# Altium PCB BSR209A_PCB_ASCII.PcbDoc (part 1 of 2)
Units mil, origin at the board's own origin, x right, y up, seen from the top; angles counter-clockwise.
Board outline 3820.03 x 2030.03 mil, 4 copper layers (Top Layer, MidLayer1, MidLayer2, Bottom Layer), stack 59.4 mil thick; 68 components, 18 nets, 122 pads, 73 vias.
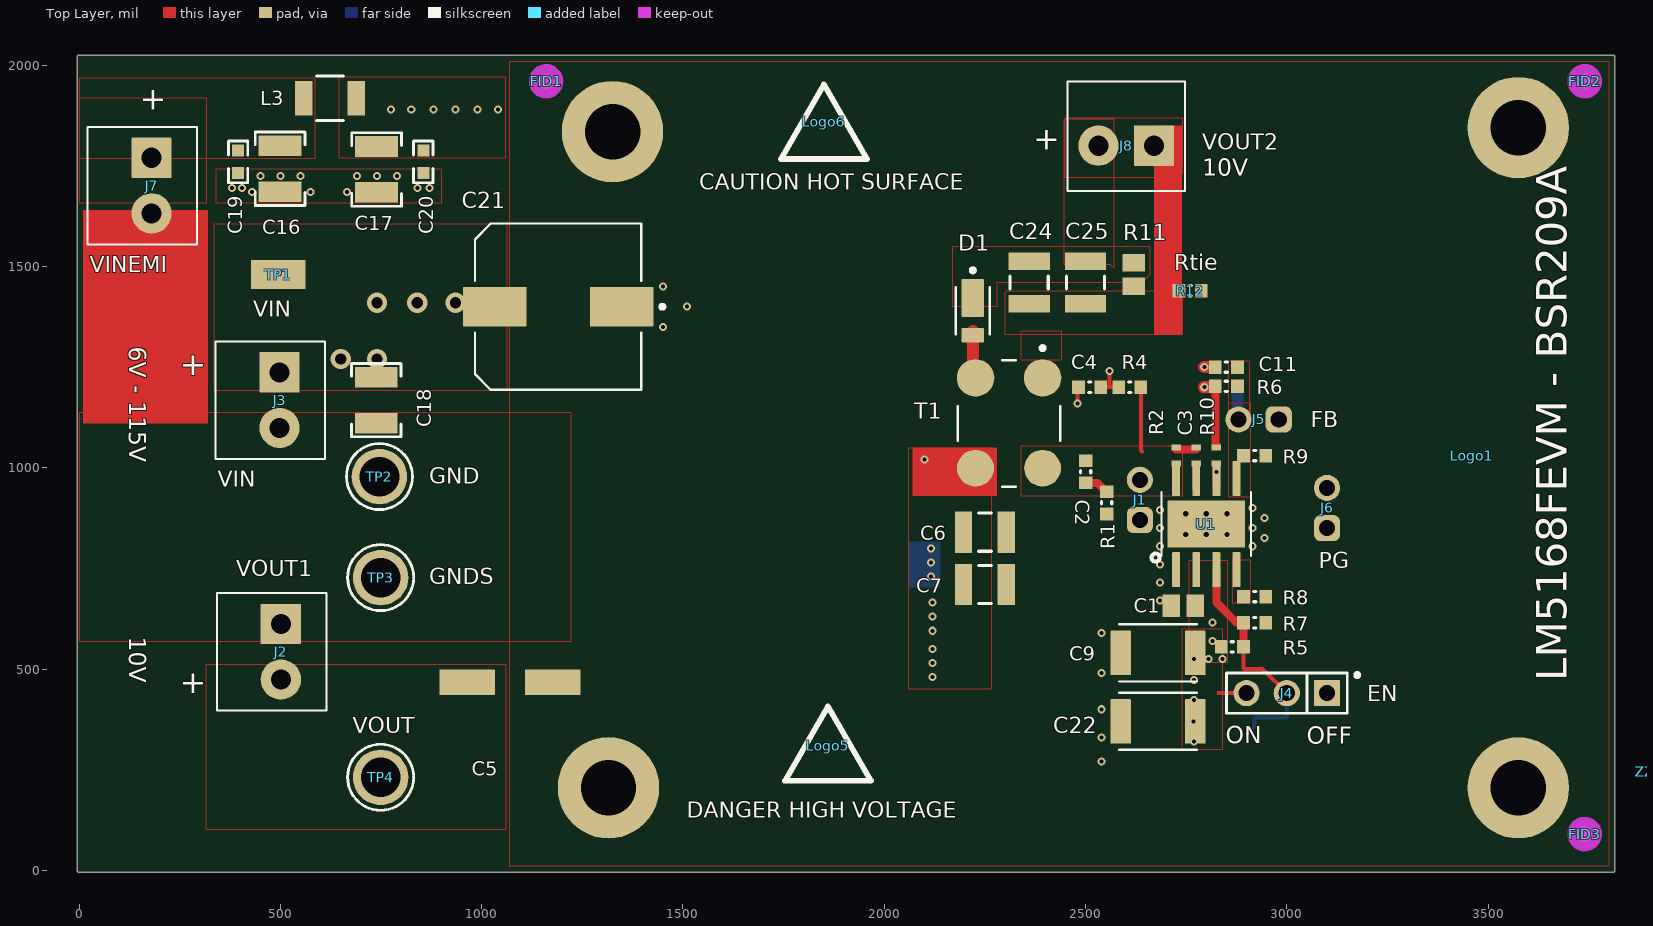
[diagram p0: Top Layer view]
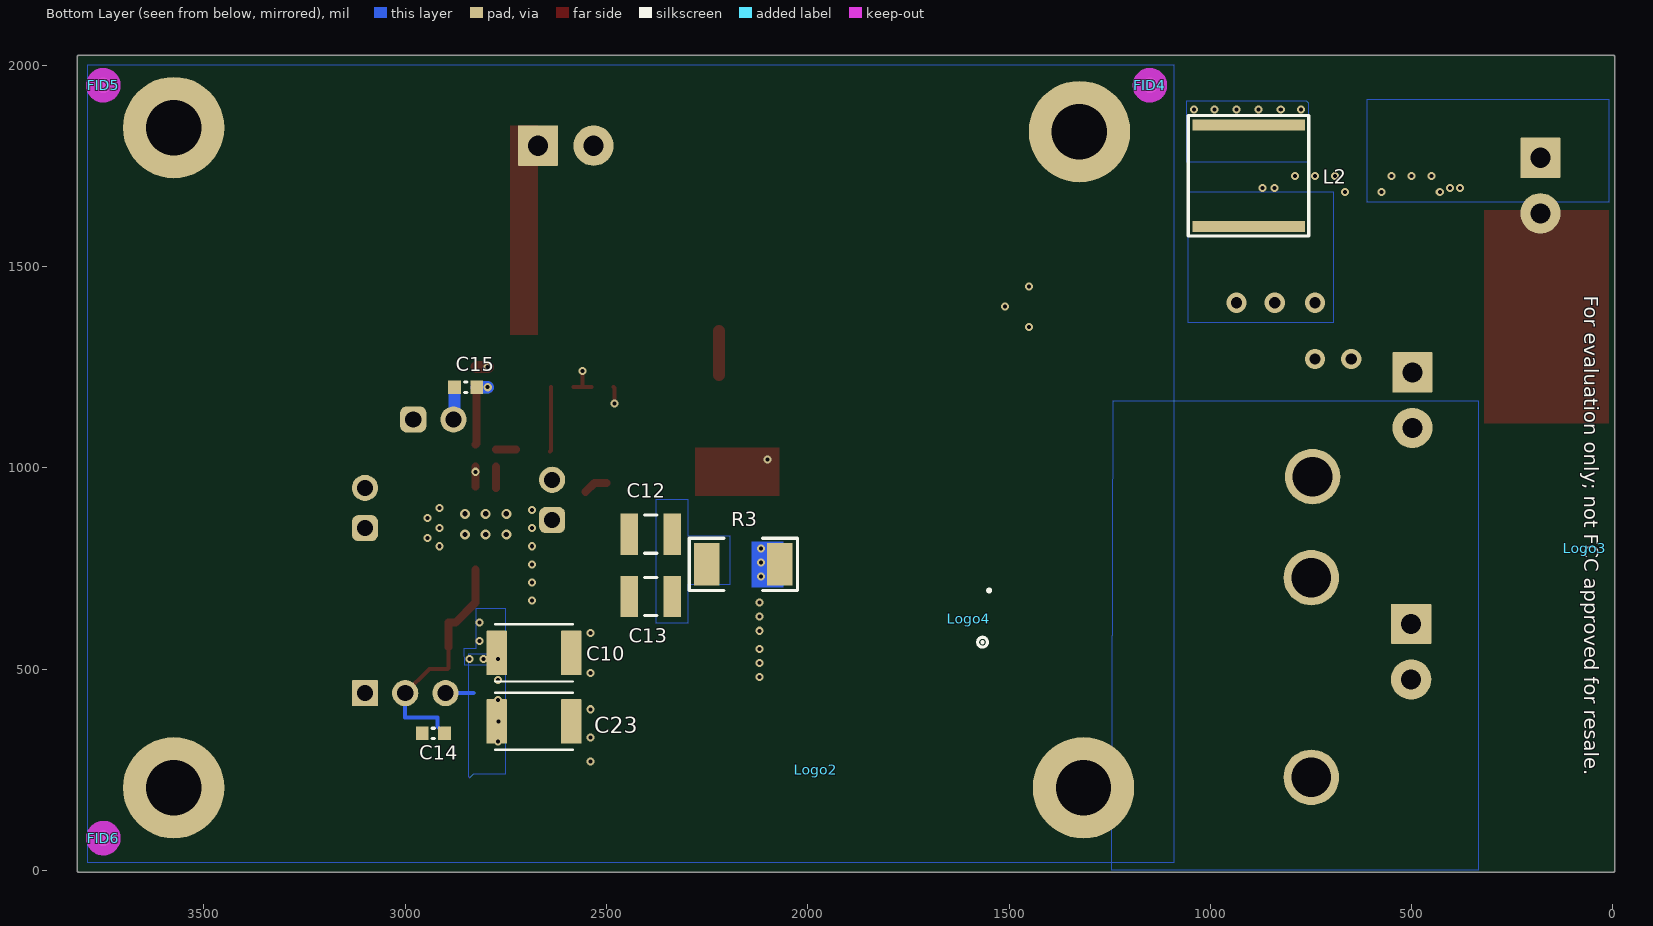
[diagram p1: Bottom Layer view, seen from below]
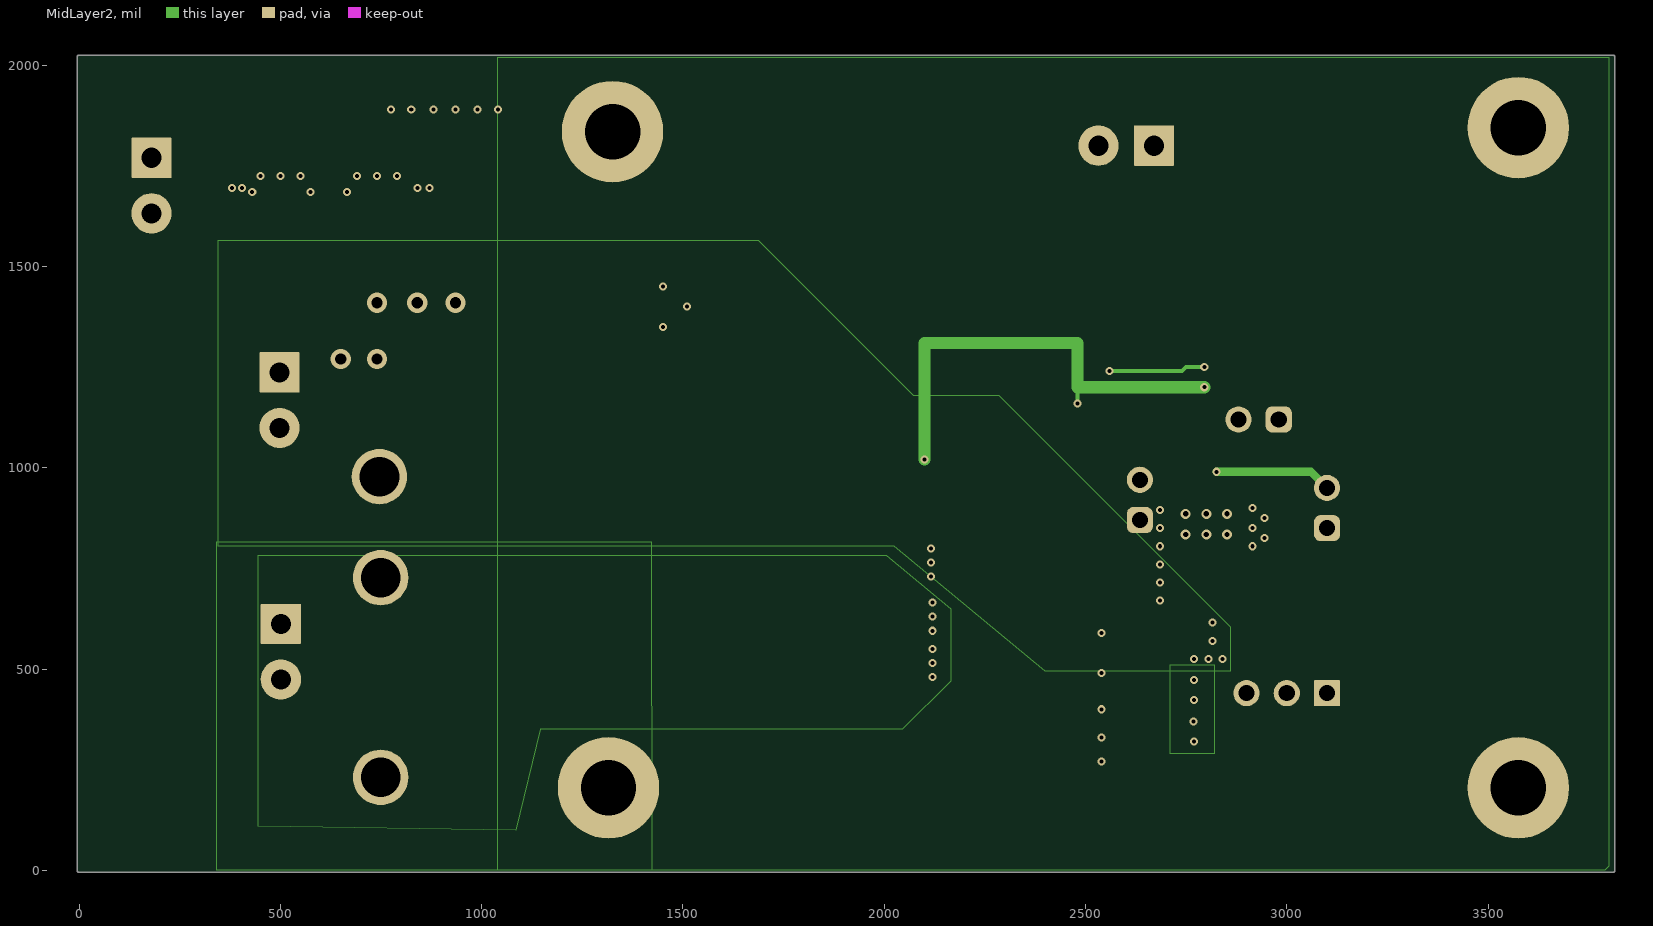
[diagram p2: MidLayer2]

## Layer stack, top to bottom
Top Solder: solder mask 0.4, Solder Resist, Dk 3.5
Top Layer: signal copper 2.8
Dielectric1: core 10, FR-4, Dk 4.8
MidLayer1: signal copper 1.4
Dielectric2: prepreg 31, FR-4, Dk 4.8
MidLayer2: signal copper 1.4
Dielectric3: core 10, FR-4, Dk 4.8
Bottom Layer: signal copper 2.8
Bottom Solder: solder mask 0.4, Solder Resist, Dk 3.5

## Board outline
0,-5.01 cw(c0,0) -5.02,0 -5.02,2020 cw(c0,2020) 0,2025.02 3810,2025.02 cw(c3810,2020) 3815.02,2020 3815.02,0 cw(c3810,0) 3810,-5.01 318,-5.01 cw(c318,0) 316.5,-4.79 cw(c315,0) 315,-5.01

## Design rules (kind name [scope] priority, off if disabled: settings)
AcuteAngle [All] p0: scope1count=1 scope1_0_kind=Board scope1_0_value=Board scope2count=1 scope2_0_kind=Board scope2_0_value=Board commentlength=0 minimum=4.50000000000000E+0001
AcuteAngle [All] p1: minimum=4.50000000000000E+0001 checktracksonly=TRUE
AssemblyTestPointUsage [All] p0: scope1count=1 scope1_0_kind=Board scope1_0_value=Board scope2count=1 scope2_0_kind=Board scope2_0_value=Board commentlength=0
AssemblyTestPointUsage [All] p1: valid=2
AssemblyTestpoint [All] p0: scope1count=1 scope1_0_kind=Board scope1_0_value=Board scope2count=1 scope2_0_kind=Board scope2_0_value=Board commentlength=0
BoardOutlineClearance [All] p0 off: scope1count=1 scope1_0_kind=Board scope1_0_value=Board scope2count=1 scope2_0_kind=Board scope2_0_value=Board commentlength=172 gap=20 // Protel DXP Scope 1 Expression Was: OnCopper and Not InComponentClass('Logo') and not InComponentClass('FiducialMark') and not InRegion(1000,500,4000,800) and not InPoly
BoardOutlineClearance BoardOutlineClearance_Poly [All] p0 off: scope1count=1 scope1_0_kind=Board scope1_0_value=Board scope2count=1 scope2_0_kind=Board scope2_0_value=Board commentlength=58 gap=15 // Protel DXP Scope 1 Expression Was: OnCopper and IsPoly
BoardOutlineClearance BoardOutlineClearance_MountingHoles [All] p0 off: scope1count=1 scope1_0_kind=Board scope1_0_value=Board scope2count=1 scope2_0_kind=Board scope2_0_value=Board commentlength=86 gap=40 // Protel DXP Scope 1 Expression Was: OnCopper and InComponentClass('Mounting Holes')
BoardOutlineClearance BoardOutlineClearance_MountingHoles [OnCopper and InComponentClass('Mounting Holes')] p1: gap=40 ignorepadtopadclearanceinfootprint=FALSE
BoardOutlineClearance BoardOutlineClearance_Poly [OnCopper and IsPoly] p2: gap=15 ignorepadtopadclearanceinfootprint=FALSE
BoardOutlineClearance [OnCopper and Not InComponentClass('Logo') and not InComponentClass('FiducialMark') and not InRegion(1000,500,4000,800) and not InPoly] p3: gap=20 ignorepadtopadclearanceinfootprint=FALSE
Clearance [All] p0: scope1count=1 scope1_0_kind=Board scope1_0_value=Board scope2count=1 scope2_0_kind=Board scope2_0_value=Board commentlength=0 gap=5
Clearance Clearance_FiducialMark [All] p0 off: scope1count=1 scope1_0_kind=Board scope1_0_value=Board scope2count=1 scope2_0_kind=Board scope2_0_value=Board commentlength=81 gap=0 // Protel DXP Scope 2 Expression Was: IsPad and InComponentClass('FiducialMark')
Clearance Clearance_Poly [All] p0 off: scope1count=1 scope1_0_kind=Board scope1_0_value=Board scope2count=1 scope2_0_kind=Board scope2_0_value=Board commentlength=48 gap=10 // Protel DXP Scope 1 Expression Was: InPolygon
Clearance Clearance_Keepouts [All] p0 off: scope1count=1 scope1_0_kind=Board scope1_0_value=Board scope2count=1 scope2_0_kind=Board scope2_0_value=Board commentlength=99 gap=0 // Protel DXP Scope 2 Expression Was: ((IsTrack Or IsArc) And Not InPoly) And IsFree and IsKeepOut
Clearance Clearance_Keepouts [((IsTrack Or IsArc) And Not InPoly) And IsFree and IsKeepOut vs ((IsTrack Or IsArc) And Not InPoly) And IsFree and IsKeepOut] p1: gap=0 ignorepadtopadclearanceinfootprint=TRUE
Clearance Clearance_Poly [InPolygon] p2: gap=10 ignorepadtopadclearanceinfootprint=TRUE except(0: Arc-Hole Track-Hole SMDPad-Hole THPad-Hole Via-Hole Fill-Hole Poly-Hole Region-Hole Text-Hole)
Clearance Clearance_FiducialMark [IsKeepOut and InComponentClass('FiducialMark') vs IsPad and InComponentClass('FiducialMark')] p3: gap=0 ignorepadtopadclearanceinfootprint=TRUE
Clearance [All] p4: gap=5 ignorepadtopadclearanceinfootprint=TRUE except(0: Arc-Hole Track-Hole SMDPad-Hole THPad-Hole Via-Hole Fill-Hole Poly-Hole Region-Hole Text-Hole)
ComponentClearance [All] p0: scope1count=1 scope1_0_kind=Board scope1_0_value=Board scope2count=1 scope2_0_kind=Board scope2_0_value=Board commentlength=0 gap=10 collisioncheckmode=3
ComponentClearance ComponentClearance_THtoTH [All] p0 off: scope1count=1 scope1_0_kind=Board scope1_0_value=Board scope2count=1 scope2_0_kind=Board scope2_0_value=Board commentlength=54 gap=10 collisioncheckmode=3 // Protel DXP Scope 2 Expression Was: IsThruComponent
ComponentClearance ComponentClearance_THtoSMT [All] p0 off: scope1count=1 scope1_0_kind=Board scope1_0_value=Board scope2count=1 scope2_0_kind=Board scope2_0_value=Board commentlength=53 gap=10 collisioncheckmode=3 // Protel DXP Scope 2 Expression Was: IsSMTComponent
ComponentClearance ComponentClearance_SmallPassives [All] p0 off: scope1count=1 scope1_0_kind=Board scope1_0_value=Board scope2count=1 scope2_0_kind=Board scope2_0_value=Board commentlength=508 gap=10 collisioncheckmode=3 // Protel DXP Scope 2 Expression Was: HasFootprint('0201*') or HasFootprint('0402*') or HasFootprint('0508') or HasFootprint('0603*') or HasFootprint('0612') or HasFootprint('0805*') or HasFootprint('0815*') or HasFootprint('0830*') or HasFootprint('1206*') or HasFootprint('1210*') or HasFootprint('1808*') or HasFootprint('1812*') or HasFootprint('1825*') or HasFootprint('2010*') or HasFootprint('2220*') or HasFootprint('2225*') or HasFootprint('2512*') or HasFootprint('2728*') or HasFootprint('3518*')
ComponentClearance ComponentClearance_MountingHoles [All] p0: scope1count=1 scope1_0_kind=ComponentClass scope1_0_value="Mounting Holes" scope2count=1 scope2_0_kind=Board scope2_0_value=Board commentlength=0 gap=10 collisioncheckmode=3
ComponentClearance ComponentClearance_ScrewToNut [All] p0 off: scope1count=1 scope1_0_kind=Board scope1_0_value=Board scope2count=1 scope2_0_kind=Board scope2_0_value=Board commentlength=71 gap=5 collisioncheckmode=3 // Protel DXP Scope 2 Expression Was: (HasFootprint('Keystone_1902C'))
ComponentClearance ComponentClearance_Logo [All] p0: scope1count=1 scope1_0_kind=ComponentClass scope1_0_value=Logo scope2count=1 scope2_0_kind=Board scope2_0_value=Board commentlength=0 gap=10 collisioncheckmode=3
ComponentClearance ComponentClearance_Shunt [All] p0: scope1count=1 scope1_0_kind=ComponentClass scope1_0_value=Header scope2count=1 scope2_0_kind=ComponentClass scope2_0_value=Shunt commentlength=0 gap=0 collisioncheckmode=3
ComponentClearance ComponentClearance_MountingHoles_FiducialMarks [All] p0: scope1count=1 scope1_0_kind=ComponentClass scope1_0_value="Mounting Holes" scope2count=1 scope2_0_kind=ComponentClass scope2_0_value=FiducialMark commentlength=0 gap=10 collisioncheckmode=3
ComponentClearance ComponentClearance_MountingHoles_FiducialMarks [InComponentClass('Mounting Holes') vs InComponentClass('FiducialMark')] p1: gap=10 collisioncheckmode=3 verticalgap=10 showdistances=FALSE
ComponentClearance ComponentClearance_Shunt [InComponentClass('Header') vs InComponentClass('Shunt')] p2: gap=0 collisioncheckmode=3 verticalgap=0 showdistances=FALSE
ComponentClearance ComponentClearance_Logo [InComponentClass('Logo')] p3: gap=10 collisioncheckmode=3 verticalgap=10 showdistances=FALSE
ComponentClearance ComponentClearance_ScrewToNut [(HasFootprint('NY PMS 440 0025 PH')) vs (HasFootprint('Keystone_1902C'))] p4: gap=5 collisioncheckmode=3 verticalgap=10 showdistances=FALSE
ComponentClearance ComponentClearance_MountingHoles [InComponentClass('Mounting Holes')] p5: gap=10 collisioncheckmode=3 verticalgap=100000 showdistances=FALSE
ComponentClearance ComponentClearance_SmallPassives [HasFootprint('0201*') or HasFootprint('0402*') or HasFootprint('0508') or HasFootprint('0603*') or HasFootprint('0612') or HasFootprint('0805*') or HasFootprint('0815*') or HasFootprint('0830*') or HasFootprint('1206*') or HasFootprint('1210*') or HasFootprint('1808*') or HasFootprint('1812*') or HasFootprint('1825*') or HasFootprint('2010*') or HasFootprint('2220*') or HasFootprint('2225*') or HasFootprint('2512*') or HasFootprint('2728*') or HasFootprint('3518*') vs HasFootprint('0201*') or HasFootprint('0402*') or HasFootprint('0508') or HasFootprint('0603*') or HasFootprint('0612') or HasFootprint('0805*') or HasFootprint('0815*') or HasFootprint('0830*') or HasFootprint('1206*') or HasFootprint('1210*') or HasFootprint('1808*') or HasFootprint('1812*') or HasFootprint('1825*') or HasFootprint('2010*') or HasFootprint('2220*') or HasFootprint('2225*') or HasFootprint('2512*') or HasFootprint('2728*') or HasFootprint('3518*')] p6: gap=10 collisioncheckmode=3 verticalgap=10 showdistances=FALSE
ComponentClearance ComponentClearance_THtoSMT [IsThruComponent vs IsSMTComponent] p7: gap=10 collisioncheckmode=3 verticalgap=30 showdistances=FALSE
ComponentClearance ComponentClearance_THtoTH [IsThruComponent vs IsThruComponent] p8: gap=10 collisioncheckmode=3 verticalgap=30 showdistances=FALSE
ComponentClearance [All] p9: gap=10 collisioncheckmode=3 verticalgap=30 showdistances=FALSE
DiffPairsRouting [All] p0: scope1count=1 scope1_0_kind=Board scope1_0_value=Board scope2count=1 scope2_0_kind=Board scope2_0_value=Board commentlength=0
DiffPairsRouting [All] p1: maxlimit=100 minlimit=10 mostfreqgap=10 toplayer_minwidth=15 toplayer_maxwidth=15 toplayer_prefwidth=15 midlayer1_minwidth=15 midlayer1_maxwidth=15 midlayer1_prefwidth=15 midlayer2_minwidth=15 midlayer2_maxwidth=15 midlayer2_prefwidth=15 bottomlayer_minwidth=15 bottomlayer_maxwidth=15 bottomlayer_prefwidth=15 maxuncoupledlength=1000
FabricationTestPointUsage TestPointUsage [All] p0: scope1count=1 scope1_0_kind=Board scope1_0_value=Board scope2count=1 scope2_0_kind=Board scope2_0_value=Board commentlength=0 valid=2 allowmultiple=FALSE
FabricationTestPointUsage TestPointUsage [All] p1: valid=2 allowmultiple=FALSE
FabricationTestpoint Testpoint [All] p0: scope1count=1 scope1_0_kind=Board scope1_0_value=Board scope2count=1 scope2_0_kind=Board scope2_0_value=Board commentlength=0 side=3 testpointundercomponent=TRUE minsize=40 maxsize=100 preferedsize=60 minholesize=0 maxholesize=40 preferedholesize=32 testpointgrid=1
FabricationTestpoint Testpoint [All] p1: side=3 testpointundercomponent=TRUE minsize=40 maxsize=100 preferedsize=60 minholesize=0 maxholesize=40 preferedholesize=32 testpointgrid=1 allowsidetop=TRUE allowsidebottom=TRUE usegrid=TRUE gridtolerance=0.01
FanoutControl Fanout_Small [All] p0 off: scope1count=1 scope1_0_kind=Board scope1_0_value=Board scope2count=1 scope2_0_kind=Board scope2_0_value=Board commentlength=84 // Protel DXP Scope 1 Expression Was: (CompPinCount < 5)   Fanout_Small (Default Rule)
FanoutControl Fanout_Default [All] p0: scope1count=1 scope1_0_kind=Board scope1_0_value=Board scope2count=1 scope2_0_kind=Board scope2_0_value=Board commentlength=30 // Fanout_Default (Default Rule)
FanoutControl Fanout_SOIC [All] p0 off: scope1count=1 scope1_0_kind=Board scope1_0_value=Board scope2count=1 scope2_0_kind=Board scope2_0_value=Board commentlength=71 // Protel DXP Scope 1 Expression Was: IsSOIC   Fanout_SOIC (Default Rule)
FanoutControl Fanout_BGA [All] p0 off: scope1count=1 scope1_0_kind=Board scope1_0_value=Board scope2count=1 scope2_0_kind=Board scope2_0_value=Board commentlength=69 // Protel DXP Scope 1 Expression Was: IsBGA   Fanout_BGA (Default Rule)
FanoutControl Fanout_LCC [All] p0 off: scope1count=1 scope1_0_kind=Board scope1_0_value=Board scope2count=1 scope2_0_kind=Board scope2_0_value=Board commentlength=69 // Protel DXP Scope 1 Expression Was: IsLCC   Fanout_LCC (Default Rule)
FanoutControl Fanout_LCC [IsLCC] p1: bgadir=Out bgaviamode=Centered fanoutstyle=Auto fanoutdirection=Alternating viagrid=1 // Fanout_LCC (Default Rule)
FanoutControl Fanout_BGA [IsBGA] p2: bgadir=Out bgaviamode=Centered fanoutstyle=Auto fanoutdirection=Alternating viagrid=1 // Fanout_BGA (Default Rule)
FanoutControl Fanout_Default [All] p4: bgadir=Out bgaviamode=Centered fanoutstyle=Auto fanoutdirection=Alternating viagrid=1 // Fanout_Default (Default Rule)
FanoutControl Fanout_Small [(CompPinCount < 5)] p5: bgadir=Out bgaviamode=Centered fanoutstyle=Auto fanoutdirection=OutThenIn viagrid=1 // Fanout_Small (Default Rule)
Height [All] p0: scope1count=1 scope1_0_kind=Board scope1_0_value=Board scope2count=1 scope2_0_kind=Board scope2_0_value=Board commentlength=0
HoleSize [All] p0: scope1count=1 scope1_0_kind=Board scope1_0_value=Board scope2count=1 scope2_0_kind=Board scope2_0_value=Board commentlength=0 absolutevalues=TRUE maxlimit=251 minlimit=7.87 maxpercent=80.000 minpercent=20.000
HoleSize [All] p1: absolutevalues=TRUE maxlimit=251 minlimit=7.87 maxpercent=80.000 minpercent=20.000
HoleToHoleClearance [All] p0: scope1count=1 scope1_0_kind=Board scope1_0_value=Board scope2count=1 scope2_0_kind=Board scope2_0_value=Board commentlength=0
LayerPairs [All] p0: scope1count=1 scope1_0_kind=Board scope1_0_value=Board scope2count=1 scope2_0_kind=Board scope2_0_value=Board commentlength=0 enforce=TRUE
MinimumAnnularRing [All] p0: scope1count=1 scope1_0_kind=Board scope1_0_value=Board scope2count=1 scope2_0_kind=Board scope2_0_value=Board commentlength=0 minimumring=5
MinimumAnnularRing MinimumAnnularRing_ThermalPadVias [All] p0 off: scope1count=1 scope1_0_kind=Board scope1_0_value=Board scope2count=1 scope2_0_kind=Board scope2_0_value=Board commentlength=63 minimumring=5 // Protel DXP Scope 1 Expression Was: IsVia and InAnyComponent
MinimumAnnularRing MinimumAnnularRing_ThermalPadVias [IsVia and InAnyComponent] p1: minimumring=5
MinimumAnnularRing [All] p2: minimumring=5
MinimumSolderMaskSliver [All] p0: scope1count=1 scope1_0_kind=Board scope1_0_value=Board scope2count=1 scope2_0_kind=Board scope2_0_value=Board commentlength=0
MinimumSolderMaskSliver MinimumSolderMaskSliver_Logo [All] p0: scope1count=1 scope1_0_kind=ComponentClass scope1_0_value=Logo scope2count=1 scope2_0_kind=ComponentClass scope2_0_value=Logo commentlength=0
MinimumSolderMaskSliver MinimumSolderMaskSliver_Logo [InComponentClass('Logo') vs InComponentClass('Logo')] p1: minsoldermaskwidth=0.7
MinimumSolderMaskSliver [All] p2: minsoldermaskwidth=3.94
NetAntennae [All] p0: scope1count=1 scope1_0_kind=Board scope1_0_value=Board scope2count=1 scope2_0_kind=Board scope2_0_value=Board commentlength=0
PasteMaskExpansion [All] p0: scope1count=1 scope1_0_kind=Board scope1_0_value=Board scope2count=1 scope2_0_kind=Board scope2_0_value=Board commentlength=0 expansion=0
PlaneClearance [All] p0: scope1count=1 scope1_0_kind=Board scope1_0_value=Board scope2count=1 scope2_0_kind=Board scope2_0_value=Board commentlength=0 clearance=9.84
PlaneClearance PlaneClearance_1 [All] p0: scope1count=1 scope1_0_kind=Layer scope1_0_value=TOP scope2count=1 scope2_0_kind=Board scope2_0_value=Board commentlength=0 clearance=7.87
PlaneClearance PlaneClearance_1 [OnLayer('Top Layer')] p1: clearance=7.87
PlaneClearance [All] p2: clearance=9.84
PlaneConnect [All] p0: scope1count=1 scope1_0_kind=Board scope1_0_value=Board scope2count=1 scope2_0_kind=Board scope2_0_value=Board commentlength=0 planeconnectstyle=Direct reliefexpansion=10 reliefentries=4 reliefconductorwidth=10 reliefairgap=10
PlaneConnect PlaneConnect_via [All] p0 off: scope1count=1 scope1_0_kind=Board scope1_0_value=Board scope2count=1 scope2_0_kind=Board scope2_0_value=Board commentlength=44 planeconnectstyle=Direct reliefexpansion=20 reliefentries=4 reliefconductorwidth=10 reliefairgap=10 // Protel DXP Scope 1 Expression Was: IsVia
PlaneConnect PlaneConnect_via [IsVia] p1: planeconnectstyle=Direct reliefexpansion=20 reliefentries=4 reliefconductorwidth=10 reliefairgap=10
PlaneConnect [All] p2: planeconnectstyle=Direct reliefexpansion=10 reliefentries=4 reliefconductorwidth=10 reliefairgap=10
PolygonConnect [All] p0: scope1count=1 scope1_0_kind=Board scope1_0_value=Board scope2count=1 scope2_0_kind=Board scope2_0_value=Board commentlength=0 connectstyle=Relief reliefconductorwidth=30 reliefentries=4 polygonreliefangle="90 Angle"
PolygonConnect PolygonConnect_poly [All] p0 off: scope1count=1 scope1_0_kind=Board scope1_0_value=Board scope2count=1 scope2_0_kind=Board scope2_0_value=Board commentlength=45 connectstyle=Direct reliefconductorwidth=30 reliefentries=4 polygonreliefangle="90 Angle" // Protel DXP Scope 1 Expression Was: IsPoly
PolygonConnect PolygonConnect_1 [All] p0: scope1count=1 scope1_0_kind=Footprint scope1_0_value=HARWIN_S1911-46R scope2count=1 scope2_0_kind=Board scope2_0_value=Board commentlength=0 connectstyle=Direct reliefconductorwidth=39.37 reliefentries=4 polygonreliefangle="90 Angle"
PolygonConnect PolygonConnect_Via [All] p0 off: scope1count=1 scope1_0_kind=Board scope1_0_value=Board scope2count=1 scope2_0_kind=Board scope2_0_value=Board commentlength=44 connectstyle=Direct reliefconductorwidth=10 reliefentries=4 polygonreliefangle="90 Angle" // Protel DXP Scope 1 Expression Was: IsVia
PolygonConnect PolygonConnect_logo [All] p0: scope1count=1 scope1_0_kind=Component scope1_0_value=Logo1 scope2count=1 scope2_0_kind=Board scope2_0_value=Board commentlength=0 connectstyle=Direct reliefconductorwidth=10 reliefentries=4 polygonreliefangle="90 Angle"
PolygonConnect PolygonConnect_tp [All] p0 off: scope1count=1 scope1_0_kind=Board scope1_0_value=Board scope2count=1 scope2_0_kind=Board scope2_0_value=Board commentlength=145 connectstyle=Direct reliefconductorwidth=10 reliefentries=4 polygonreliefangle="90 Angle" // Protel DXP Scope 1 Expression Was: (InComponent('TP*') or InComponent('J4*') or InComponent('J3*') or InComponent('X7') or InComponent('X9'))
PolygonConnect PolygonConnect_tp [(InComponent('TP*') or InComponent('J4*') or InComponent('J3*') or InComponent('X7') or InComponent('X9'))] p1: connectstyle=Direct reliefconductorwidth=10 reliefentries=4 polygonreliefangle="90 Angle" airgapwidth=10
PolygonConnect PolygonConnect_logo [InComponent('Logo1')] p2: connectstyle=Direct reliefconductorwidth=10 reliefentries=4 polygonreliefangle="90 Angle" airgapwidth=10
PolygonConnect PolygonConnect_Via [IsVia] p3: connectstyle=Direct reliefconductorwidth=10 reliefentries=4 polygonreliefangle="90 Angle" airgapwidth=10
PolygonConnect PolygonConnect_1 [HasFootprint('HARWIN_S1911-46R')] p4: connectstyle=Direct reliefconductorwidth=39.37 reliefentries=4 polygonreliefangle="90 Angle" airgapwidth=7.87
PolygonConnect PolygonConnect_poly [IsPoly] p5: connectstyle=Direct reliefconductorwidth=30 reliefentries=4 polygonreliefangle="90 Angle" airgapwidth=8
PolygonConnect [All] p6: connectstyle=Relief reliefconductorwidth=30 reliefentries=4 polygonreliefangle="90 Angle" airgapwidth=8
RoutingCorners [All] p0: scope1count=1 scope1_0_kind=Board scope1_0_value=Board scope2count=1 scope2_0_kind=Board scope2_0_value=Board commentlength=0 cornerstyle=45-Degree minsetback=100 maxsetback=100
RoutingLayers [All] p0: scope1count=1 scope1_0_kind=Board scope1_0_value=Board scope2count=1 scope2_0_kind=Board scope2_0_value=Board commentlength=0 top layer=Automatic mid layer 1=Automatic mid layer 2=Automatic bottom layer=Automatic
RoutingPriority [All] p0: scope1count=1 scope1_0_kind=Board scope1_0_value=Board scope2count=1 scope2_0_kind=Board scope2_0_value=Board commentlength=0
RoutingTopology [All] p0: scope1count=1 scope1_0_kind=Board scope1_0_value=Board scope2count=1 scope2_0_kind=Board scope2_0_value=Board commentlength=0 topology=Shortest
RoutingVias [All] p0: scope1count=1 scope1_0_kind=Board scope1_0_value=Board scope2count=1 scope2_0_kind=Board scope2_0_value=Board commentlength=0 holewidth=16 width=34 viastyle="Through Hole" minholewidth=7 minwidth=20 maxholewidth=40 maxwidth=65
RoutingVias ThermalPadVias [All] p0 off: scope1count=1 scope1_0_kind=Board scope1_0_value=Board scope2count=1 scope2_0_kind=Board scope2_0_value=Board commentlength=63 holewidth=7.87 width=19.68 viastyle="Through Hole" minholewidth=7.87 minwidth=19.68 maxholewidth=12.99 maxwidth=25 // Protel DXP Scope 1 Expression Was: IsVia and InAnyComponent
RoutingVias ThermalPadVias [IsVia and InAnyComponent] p1: holewidth=7.87 width=19.68 viastyle="Through Hole" minholewidth=7.87 minwidth=19.68 maxholewidth=12.99 maxwidth=25
RoutingVias [All] p2: holewidth=16 width=34 viastyle="Through Hole" minholewidth=7 minwidth=20 maxholewidth=40 maxwidth=65
ShortCircuit [All] p0: scope1count=1 scope1_0_kind=Board scope1_0_value=Board scope2count=1 scope2_0_kind=Board scope2_0_value=Board commentlength=0 allowed=FALSE
SilkToBoardRegionClearance [All] p0: scope1count=1 scope1_0_kind=Board scope1_0_value=Board scope2count=1 scope2_0_kind=Board scope2_0_value=Board commentlength=0
SilkToSilkClearance [All] p0: scope1count=1 scope1_0_kind=Board scope1_0_value=Board scope2count=1 scope2_0_kind=Board scope2_0_value=Board commentlength=0
SilkToSilkClearance SilkToSilkClearance_Pb-FreeLogo [All] p0 off: scope1count=1 scope1_0_kind=Board scope1_0_value=Board scope2count=1 scope2_0_kind=Board scope2_0_value=Board commentlength=120 // Protel DXP Scope 2 Expression Was: (HasFootprint('Pb-Free_Overlay_Medium') OR HasFootprint('Pb-Free_Overlay_Small'))
SilkToSilkClearance SilkToSilkClearance_Pb-FreeLogo [(HasFootprint('Pb-Free_Overlay_Medium') OR HasFootprint('Pb-Free_Overlay_Small')) vs (HasFootprint('Pb-Free_Overlay_Medium') OR HasFootprint('Pb-Free_Overlay_Small'))] p1: silktosilkclearance=0
SilkToSilkClearance [All] p2: silktosilkclearance=3
SilkToSolderMaskClearance "Silk to Solder Mask Opening" [All] p0: scope1count=1 scope1_0_kind=Board scope1_0_value=Board scope2count=1 scope2_0_kind=Board scope2_0_value=Board commentlength=0
SilkToSolderMaskClearance SilkToComponentPadClearance [All] p0 off: scope1count=1 scope1_0_kind=Board scope1_0_value=Board scope2count=1 scope2_0_kind=Board scope2_0_value=Board commentlength=87 // Protel DXP Scope 1 Expression Was: (IsPad or IsFill or IsRegion) and InAnycomponent
SilkToSolderMaskClearance SilkToComponentPadClearance [(IsPad or IsFill or IsRegion) and InAnycomponent] p1: minsilkscreentomaskgap=5 clearancetoexposedcopper=TRUE
SilkToSolderMaskClearance "Silk to Solder Mask Opening" [All] p2: minsilkscreentomaskgap=4 clearancetoexposedcopper=FALSE
SolderMaskExpansion [All] p0: scope1count=1 scope1_0_kind=Board scope1_0_value=Board scope2count=1 scope2_0_kind=Board scope2_0_value=Board commentlength=0 expansion=1.97
SolderMaskExpansion [All] p1: expansion=1.97
UnRoutedNet [All] p0: scope1count=1 scope1_0_kind=Board scope1_0_value=Board scope2count=1 scope2_0_kind=Board scope2_0_value=Board commentlength=0
UnpouredPolygon [All] p0: scope1count=1 scope1_0_kind=Board scope1_0_value=Board scope2count=1 scope2_0_kind=Board scope2_0_value=Board commentlength=0
Width [All] p0: scope1count=1 scope1_0_kind=Board scope1_0_value=Board scope2count=1 scope2_0_kind=Board scope2_0_value=Board commentlength=0 maxlimit=100 minlimit=6 preferedwidth=10
Width [All] p1: maxlimit=100 minlimit=6 preferedwidth=10 checkconnectedcopper=TRUE
15 further rules are at their usual default settings.

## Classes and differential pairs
component class BSR209A_sch: 30 500kHz C1 C2 C3 C4 C5 C6 C7 C9 C10 C11 C12 C13 C14 C15 C16 C17 C18 C19 C20 C21 C22 C23 C24 C25 CIN1 COUT2 COUT3 D1 gnd J1 J2 J3 J4 J5 J6 J7 J8 L2 L3 R1 R2 R3 R4 R5 R6 R7 R8 R9 R10 R11 R12 T1 TP1 TP2 TP3 TP4 TPCLK180 U1 vin Vout
component class AssemblyNote: ZZ2 ZZ3 ZZ4
component class BSR209A_Hardware: !PCB FID1 FID2 FID3 FID4 FID5 FID6 Logo1 Logo2 Logo3 Logo4 Logo5 Logo6 ZZ2 ZZ3 ZZ4
component class Logo: Logo1
component class Header: J1 J4 J5 J6
component class FiducialMark: FID1 FID2 FID3 FID4 FID5 FID6

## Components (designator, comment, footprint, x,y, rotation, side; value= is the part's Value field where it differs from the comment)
C1 "C2012X7T2E104K125AA" 0805L 2742.79,657.21 r180 top
C2 "GRM188R72D102KW07D" 0603L 2500,990 r90 top
C3 "GCM155R71H222KA37D" 0402S 2775,1030 r270 top
C4 "CR" 0603L 2510,1200 r0 top
C5 "UWT1E101MCL1GS" UWT_630x770 1070,467 r0 top
C6 "GRT32ER61E226KE13L" 1210_270L 2250,840 r0 top
C7 "GRT32ER61E226KE13L" 1210_270L 2250,710 r0 top
C9 "CGA8P3X7T2E105K250KE" FP-CGA8P3X7T2E105K250KE_1812-MFG 2680,540 r0 top
C10 "CGA8P3X7T2E105K250KE" FP-CGA8P3X7T2E105K250KE_1812-MFG 2680,540 r0 bottom
C11 "C0603C560J5GACTU" 0603L 2850,1250 r0 top
C12 "COUT3" 1210_270L 2390,835 r0 bottom
C13 "COUT4" 1210_270L 2390,680 r0 bottom
C14 "CEN" 0603L 2930,340 r0 bottom
C15 "CFF" 0603L 2850,1200 r0 bottom
C16 "CGA6M3X7S2A475K200AB" 1210_220 499,1743 r270 top
C17 "CGA6M3X7S2A475K200AB" 1210_220 739,1741 r270 top
C18 "CGA6M3X7S2A475K200AB" 1210_220 738,1168 r270 top
C19 "HMK107B7104KAHT" 0603_HV 395,1760 r270 top
C20 "HMK107B7104KAHT" 0603_HV 855,1760 r270 top
C21 "ULT2C330MNL1GS" FP-ULT2C330MNL1GS_RADIAL-MFG 1190,1400 r180 top
C22 "CGA8P3X7T2E105K250KE" FP-CGA8P3X7T2E105K250KE_1812-MFG 2680,370 r0 top
C23 "CGA8P3X7T2E105K250KE" FP-CGA8P3X7T2E105K250KE_1812-MFG 2680,370 r0 bottom
C24 "GRT32ER61E226KE13L" 1210_270L 2360,1460 r270 top
C25 "GRT32ER61E226KE13L" 1210_270L 2500,1460 r270 top
D1 "SS1H20LS RVG" "FP-SS1H20LS RVG_SOD123HE-MFG" 2220,1390 r270 top
FID1 "Fiducial" Fiducial10-20 1160,1960 r90 top
FID2 "Fiducial" Fiducial10-20 3740,1960 r90 top
FID3 "Fiducial" Fiducial10-20 3740,90 r90 top
FID4 "Fiducial" Fiducial10-20 1150,1950 r90 bottom
FID5 "Fiducial" Fiducial10-20 3750,1950 r90 bottom
FID6 "Fiducial" Fiducial10-20 3750,80 r90 bottom
J1 "SW" TSW-102-07-G-S 2635,920 r90 top
J2 "VOUT1" TERM_BLK_ED555-2DS 501,612 r270 top
J3 "VIN" TERM_BLK_ED555-2DS 498,1237 r270 top
J4 "EN" Samtec_HTSW-103-07-G-S 3000,440 r180 top
J5 "FB" TSW-102-07-G-S 2930,1120 r180 top
J6 "PG" TSW-102-07-G-S 3100,900 r90 top
J7 "VINEMI" TERM_BLK_ED555-2DS 180,1770 r270 top
J8 "VOUT2" TERM_BLK_ED555-2DS 2670,1800 r180 top
L2 "MSS7341T-153MLB" MSS7341 905,1725 r270 bottom
L3 "FBMH3225HM202NT" 1210_280 623,1918 r0 top
Logo1 "Texas Instruments" TI_Stacked_Overlay_Small 3460,1030 r90 top
Logo2 "CE Mark" CE_Mark_10mm 1980,250 r180 bottom
Logo3 "FCC disclaimer" FCC_disclaimer 70,800 r270 bottom
Logo4 "WEEE logo" WEEE_Minimum 1600,625 r180 bottom
Logo5 "DANGER HIGH VOLTAGE" IEC_HighVoltage_Small 1860,310 r0 top
Logo6 "CAUTION HOT SURFACE" IEC_HotSurface_Small 1850,1860 r0 top
R1 "CRCW06031R00JNEA" 0603L 2552.2,912.8 r90 top
R2 "RBST" 0402S 2725,1030 r270 top
R3 "DNP" 2010 2160,760 r180 bottom
R4 "RC0603FR-07118KL" 0603L 2610,1200 r180 top
R5 "RC0603FR-071ML" 0603L 2865,555 r180 top
R6 "RC0603FR-07453KL" 0603L 2850,1202 r180 top
R7 "RC0603FR-07332KL" 0603L 2920,615 r180 top
R8 "RC0603FR-0733K2L" 0603L 2920,680 r180 top
R9 "RC0603FR-0761K9L" 0603L 2920,1030 r180 top
R10 "ERJ-2RKF1003X" 0402S 2825,1030 r90 top
R11 "CRCW08051K00FKEA" 0805L 2620,1480 r90 top
R12 "Rtie" 0603L 2760,1440 r0 top
T1 "LPD8035V-333MRC" FP-LPD8035V-333MRC_SMD4-MFG 2310,1110 r270 top
TP1 "VIN" Harwin_S1751-46 495,1480 r0 top
TP2 "GND" Keystone1598-2 746,978 r90 top
TP3 "GNDS" Keystone1598-2 749,727 r90 top
TP4 "VOUT" Keystone1598-2 749,231 r90 top
U1 "LM5168FQDDARQ1" DDA0008E-MFG 2800,860 r90 top
ZZ2 "These assemblies are ESD sensitive, ESD precautions shall be observed." AssemblyNote 4250,245 r90 top
ZZ3 "These assemblies must be clean and free from flux and all contaminants. Use of no clean flux is not acceptable." AssemblyNote 4070,245 r90 top
ZZ4 "These assemblies must comply with workmanship standards IPC-A-610 Class 2, unless otherwise specified." AssemblyNote 3900,245 r90 top

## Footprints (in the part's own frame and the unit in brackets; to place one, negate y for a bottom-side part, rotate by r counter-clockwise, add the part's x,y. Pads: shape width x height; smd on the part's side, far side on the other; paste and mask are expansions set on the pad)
0402S [mil] "Based on C0402S footprint from PADS legacy"
  rect 15x24 smd: 1(-20,0) 2(20,0)
0603_HV [mil] "Ernesto recommended land pattern.  26 mil between pads."
  rect 30x30 smd: 1(-28,0) 2(28,0)
  silkscreen extent -52,-24 52,24
0603L [mm] "0603 from SM-752 data"
  rect 0.8x0.85 smd: 1(-0.7,0) 2(0.7,0)
  silkscreen extent -0.07,-0.33 0.07,0.33
0805L [mm] "0805 from SM-752 data"
  rect 1.1x1.4 smd: 1(-0.75,0) 2(0.75,0)
1210_220 [mm] "1210"
  rect 1.3x2.7 smd: 1(-1.45,0) 2(1.45,0)
  silkscreen extent -2.32,-1.57 2.32,1.57
1210_270L [mm] "1210"
  rect 1.1x2.6 smd: 1(-1.35,0) 2(1.35,0)
  silkscreen extent -0.4,-1.2 0.4,1.2
1210_280 [mm] "SMD, 2-Leads, Body 3.6x2.8mm, Height 2.8mm"
  rect 1.1x2.2 smd: 1(-1.65,0) 2(1.65,0)
  silkscreen extent -0.84,-1.4 0.84,1.4
2010 [mm] "Chip Capacitor, Body 5.08x2.54mm, IPC Medium Density"
  rect 1.6x2.7 smd: 1(-2.3,0) 2(2.3,0)
  silkscreen extent -3.42,-1.65 3.42,1.65
AssemblyNote [mil] "Assembly Note"
CE_Mark_10mm [mil] "Double the minimum text height for CE Mark"
DDA0008E-MFG [mm]
  rrect20% 2.2x0.5 smd paste-1000 mask+0: 1(-2.875,1.905) 2(-2.875,0.635) 3(-2.875,-0.635) 4(-2.875,-1.905) 5(2.875,-1.905) 6(2.875,-0.635) 7(2.875,0.635) 8(2.875,1.905)
  rrect3% 2.95x4.9 smd paste-1000 mask+0: 9(0,0)
  silkscreen extent -2,-2.83 2,2.83
FCC_disclaimer [mil]
Fiducial10-20 [mm]
  round 1 smd mask+0: 1(0,0)
  Top Layer keep-out circle w1.178: c0,0 r0.5
FP-CGA8P3X7T2E105K250KE_1812-MFG [mm]
  rrect8% 1.3x2.8 smd paste+0 mask+0: 1(-2.35,0) 2(2.35,0)
  silkscreen extent -2.45,-1.8 2.45,1.8
FP-LPD8035V-333MRC_SMD4-MFG [mm]
  round 2.367 smd paste+0 mask+0: 1(-2.875,2.115) 2(-2.875,-2.115)
  round 2.325 smd paste+0 mask+0: 3(2.822,-2.115) 4(2.822,2.115)
  silkscreen extent -4.87,-3.24 4,3.24
"FP-SS1H20LS RVG_SOD123HE-MFG" [mm]
  rrect7% 2.4x1.4 smd paste+0 mask+0: 1(-0.8,0)
  rrect11% 0.9x1.4 smd paste+0 mask+0: 2(1.55,0)
  silkscreen extent -2.67,-1.07 1.5,1.07
FP-ULT2C330MNL1GS_RADIAL-MFG [mm]
  rrect4% 4x2.5 smd paste+0 mask+0: 1(-4,0) 2(4,0)
  silkscreen extent -6.7,-5.25 5.25,5.25
Harwin_S1751-46 [mm] "Test Point, Body 3.25x1.65mm"
  rect 3.45x1.85 smd: 1(0,0)
IEC_HighVoltage_Small [mil]
  silkscreen extent -107,-88 107,97
IEC_HotSurface_Small [mil]
  silkscreen extent -107,-93 107,92
Keystone1598-2 [mm] "Triple Turret"
  round 3.5 hole 2.5: 1(0,0)
  silkscreen extent -2.08,-2.08 2.08,2.08
MSS7341 [mm] "Coilcraft recommended land pattern Document 383-2 1/3/11"
  rect 0.7x7.1 smd: 1(-3.2,0) 2(3.2,0)
  silkscreen extent -3.8,-3.8 3.8,3.8
Samtec_HTSW-103-07-G-S [mm] "Samtec 100mil, 1x3, 230 mil above insulator"
  rrect6% 1.65x1.65 hole 1.016: 1(-2.54,0)
  round 1.65 hole 1.016: 2(0,0) 3(2.54,0)
  silkscreen extent -4.57,-1.27 3.81,1.27
TERM_BLK_ED555-2DS [mil]
  rrect4% 100x100 hole 50: 1(0,0)
  round 100 hole 50: 2(138,0)
  silkscreen extent -77,-159 215,113
TI_Stacked_Overlay_Small [mil]
TSW-102-07-G-S [mm] "Samtec 100mil, 1x2, 230 mil above insulator"
  rrect50% 1.65x1.65 hole 1.016: 1(-1.27,0)
  round 1.65 hole 1.016: 2(1.27,0)
UWT_630x770 [mm] "SMD, 2-Leads, Dia 6.3mm"
  rrect6% 3.5x1.6 smd: 1(-2.7,0) 2(2.7,0)
WEEE_Minimum [mil] "WEEElie bin"
  silkscreen extent 22,-71 54,74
